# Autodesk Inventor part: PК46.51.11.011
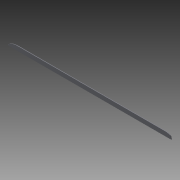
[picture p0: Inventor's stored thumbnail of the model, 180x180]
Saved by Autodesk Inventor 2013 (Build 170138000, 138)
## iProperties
Shininess: 64.0
Length Units: 11269
Angle Units: 11279
Time Units: 11290
Mass Units: 11283
Length Display Precision: 3
Angle Display Precision: 2
Compacted: True
Part Number: PК46.51.11.011
Document SubType Name: Листовой материал
Created: 2004-12
Material: Steel, Mild
Designer: =<Author>
Manufacturer: Standard
Standards Organization: Custom
Description: strip seal
Density: 7.86 g/cm^3
Sheet Metal Rule: По умолчанию
Mass: 131.382 g
Surface Area: 190.177 cm^2
Volume: 16.7152 cm^3
Density: 0.0
Volumn: 0.0
Area: 0.0
PropertySet Name: Model Information
Control State: 0
Master: False
Checked Out: False
Checked Out Date: 2008-10-15
Last Check In Date: 2008-10-15
Author: PVitaliy
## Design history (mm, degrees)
node "ФлнОтгиб1"
feature "Вырез1" dims "d10" = 2 (= Толщина), "d11" = 0
feature "Вырез2" dims "d14" = 2 (= Толщина), "d15" = 0
feature "Вырез3" dims "d18" = 2 (= Толщина), "d19" = 0
body "Solid1"
sketch "Эскиз1"
  geometry: L1 (0, 0)-(568, 0)
  constraints: 2 end point, 1 horizontal, 1 other
  dimensions: "d0" = 568 distance of L1.start L1.end
feature "Пластина1" dims "d2" = 15, "d3" = 2 (= Ширина_просечки), "d5" = 4 (= Минимальный_остаток), "d7" = 2 (= Радиус_гибки), "d8" = 2, "Толщина" = 2
feature "Изгиб1" dims "d3" = 2 (= Ширина_просечки), "d4" = 1 (= Глубина_просечки), "d5" = 4 (= Минимальный_остаток), "d6" = 2 (= Радиус_гибки), "d7" = 2 (= Радиус_гибки), "d8" = 2, "Толщина" = 2, "Зазор_стыка" = 0.01
sketch "Эскиз2"
  geometry: L1 (568, 15)-(0, 15) reference; L2 (568, 0)-(568, 15) reference; L3 (568, 0)-(563.981, 15)
  constraints: 2 end point, 1 point on line
  dimensions: "d9" = 15 deg angle of L2 L3
sketch "Эскиз3"
  geometry: L1 (563.981, 15)-(0, 15) reference; L2 (0, 0)-(0, 15) reference; A1 r 45 centre (30, -30) between (30, 15) and (0, 3.541)
  constraints: 2 point on circle, 2 point on line, 1 centre point, 1 tangent
  dimensions: "d12" = 90 diameter of A1; "d13" = 30 distance from line of A1.centre L2
sketch "Эскиз4"
  geometry: L1 (568, 0)-(563.981, 15) reference; L2 (563.981, 15)-(30, 15) reference; A1 r 45 centre (546, -30) between (565.124, 10.734) and (546, 15)
  constraints: 2 point on circle, 2 point on line, 1 centre point, 1 tangent
  dimensions: "d16" = 90 diameter of A1; "d17" = 22 horizontal distance of A1.centre L1.start
other parameters: "Радиус_гибки" = 2 (= Толщина), "Ширина_просечки" = 2 (= Толщина), "Глубина_просечки" = 1 (= 0.5 x Толщина), "Размер_высечки" = 8 (= 4 x Толщина), "Минимальный_остаток" = 4 (= 2 x Толщина), "Радиус_перехода" = 2 (= Радиус_гибки), "JacobiRadiusSize" = 2 (= Толщина), "GapSize" = 2 (= Толщина)
